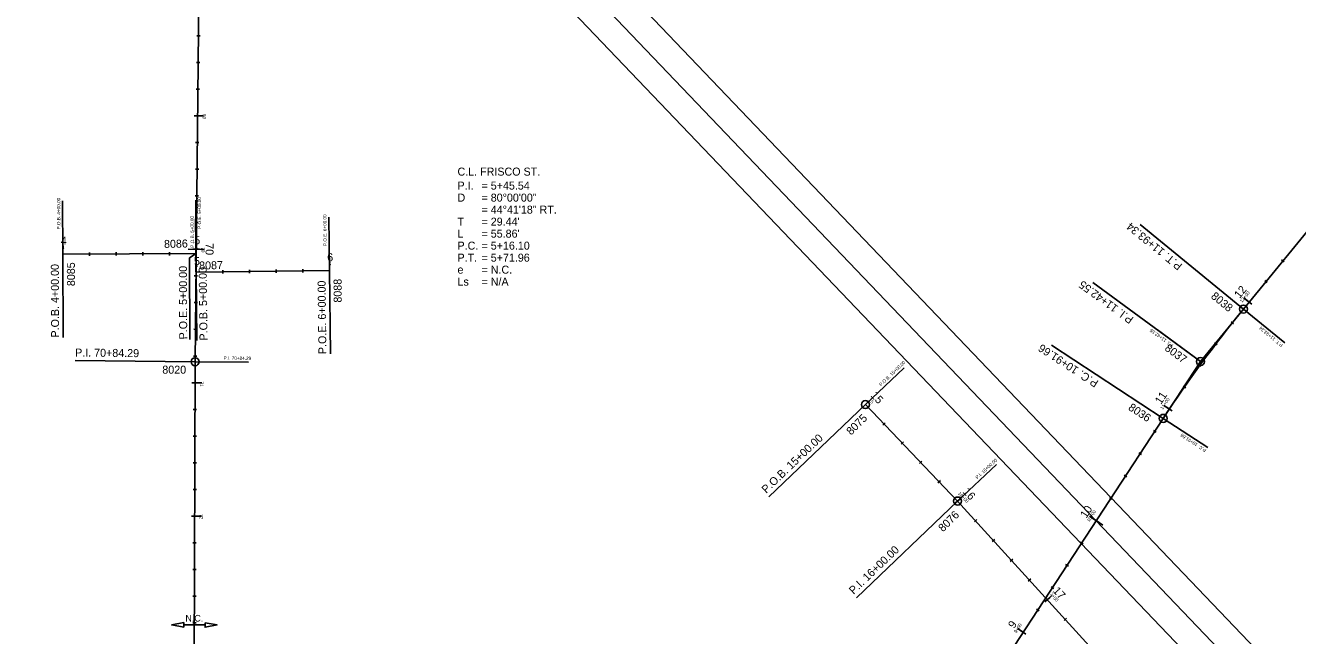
# Model space of a CAD drawing. Extents: x 1708585 to 1714116, y 541444 to 545437.
# Drawn here: x 1711863 to 1712816, y 543530 to 543987 of the extents above; entities that cross this region are included whole.
import ezdxf

# ---------------------------------------------------------------- set-up
doc = ezdxf.new("R2010")
doc.units = 0
for name, color, linetype in [('CL_Highway_2', 7, 'Continuous'), ('CL_Highway_2_40_PText', 7, 'Continuous'), ('CL_Highway_2_40_Sta', 7, 'Continuous'), ('CL_Highway_2_PText', 7, 'Continuous'), ('CL_Highway_2_Sta', 7, 'Continuous'), ('CL_Railroad', 7, 'Continuous'), ('CL_XS_1', 7, 'Continuous'), ('CL_XS_1_40_PText', 7, 'Continuous'), ('CL_XS_1_40_Sta', 7, 'Continuous'), ('CL_XS_1_PText', 7, 'Continuous'), ('CL_XS_1_Sta', 7, 'Continuous'), ('CL_XS_1_Sta_Minor_Text', 7, 'Continuous'), ('CL_XS_1_Tangent', 7, 'Continuous'), ('CL_XS_3', 7, 'Continuous'), ('CL_XS_3_40_PText', 7, 'Continuous'), ('CL_XS_3_40_Sta', 7, 'Continuous'), ('CL_XS_3_PText', 7, 'Continuous'), ('CL_XS_3_Sta', 7, 'Continuous'), ('CL_XS_3_Sta_Minor_Text', 7, 'Continuous'), ('CurveData_100', 7, 'Continuous'), ('Point_CL_Highway_2', 7, 'Continuous'), ('Point_CL_XS_1', 7, 'Continuous'), ('Point_CL_XS_3', 7, 'Continuous'), ('Point_Number', 7, 'Continuous'), ('R_SE_Slope', 7, 'Continuous')]:
    doc.layers.add(name, color=color, linetype=linetype)

msp = doc.modelspace()

# ---------------------------------------------------------------- linework, layer by layer
at = {"layer": 'CL_Highway_2'}
for p, q in [((1711994.54, 544190.95), (1711989.93, 543735.39)), ((1711989.93, 543735.39), (1711989.1, 543444.38))]:
    msp.add_line(p, q, dxfattribs=at)
at = {"layer": 'CL_Highway_2_40_PText'}
msp.add_lwpolyline([(1711989.93, 543735.39), (1712029.93, 543734.99)], dxfattribs=at)
at = {"layer": 'CL_Highway_2_40_Sta'}
for points in [[(1711993.65, 543979.66), (1711991.15, 543979.68)], [(1711993.45, 543959.66), (1711990.95, 543959.68)], [(1711993.25, 543939.66), (1711990.75, 543939.68)], [(1711994.3, 543919.65), (1711989.3, 543919.7)], [(1711992.84, 543899.66), (1711990.34, 543899.68)], [(1711992.64, 543879.66), (1711990.14, 543879.69)], [(1711992.44, 543859.66), (1711989.94, 543859.69)], [(1711992.24, 543839.66), (1711989.74, 543839.69)], [(1711993.28, 543819.65), (1711988.28, 543819.7)], [(1711991.83, 543799.66), (1711989.33, 543799.69)], [(1711991.63, 543779.67), (1711989.13, 543779.69)], [(1711991.43, 543759.67), (1711988.93, 543759.69)], [(1711991.22, 543739.67), (1711988.72, 543739.69)], [(1711992.39, 543719.67), (1711987.39, 543719.69)], [(1711991.08, 543699.68), (1711988.58, 543699.68)], [(1711991.02, 543679.68), (1711988.52, 543679.68)], [(1711990.96, 543659.68), (1711988.46, 543659.68)], [(1711990.91, 543639.68), (1711988.41, 543639.68)], [(1711992.1, 543619.67), (1711987.1, 543619.69)], [(1711990.79, 543599.68), (1711988.29, 543599.68)], [(1711990.74, 543579.68), (1711988.24, 543579.68)], [(1711990.68, 543559.68), (1711988.18, 543559.68)], [(1711990.62, 543539.68), (1711988.12, 543539.69)]]:
    msp.add_lwpolyline(points, dxfattribs=at)
at = {"layer": 'CL_Highway_2_PText'}
msp.add_lwpolyline([(1711989.93, 543735.39), (1711899.93, 543736.3)], dxfattribs=at)
at = {"layer": 'CL_Highway_2_Sta'}
for p, q in [((1711994.89, 543719.67), (1711989.89, 543719.68)), ((1711994.6, 543619.67), (1711989.6, 543619.68))]:
    msp.add_line(p, q, dxfattribs=at)
for points in [[(1711996.3, 543919.63), (1711991.8, 543919.67)], [(1711996.78, 543819.62), (1711984.78, 543819.74)]]:
    msp.add_lwpolyline(points, dxfattribs=at)
at = {"layer": 'CL_Railroad'}
for p, q in [((1710952.7, 545436.87), (1713371.13, 542906.81)), ((1710938.24, 545423.05), (1713356.67, 542892.99)), ((1710923.78, 545409.23), (1713342.21, 542879.17))]:
    msp.add_line(p, q, dxfattribs=at)
at = {"layer": 'CL_XS_1'}
for p, q in [((1712775.63, 543774.89), (1712930.47, 543963.94)), ((1712523.65, 543399.96), (1712715.52, 543692.96))]:
    msp.add_line(p, q, dxfattribs=at)
msp.add_arc((1713514.4, 543169.82), 954.93, 140.68144, 146.78172, dxfattribs=at)
at = {"layer": 'CL_XS_1_40_PText'}
for points in [[(1712775.63, 543774.89), (1712806.58, 543749.55)], [(1712743.39, 543735.53), (1712711.14, 543759.19)], [(1712715.52, 543692.96), (1712748.98, 543671.04)]]:
    msp.add_lwpolyline(points, dxfattribs=at)
at = {"layer": 'CL_XS_1_40_Sta'}
for points in [[(1712804.23, 543811.78), (1712806.17, 543810.2)], [(1712791.56, 543796.31), (1712793.49, 543794.73)], [(1712777.92, 543781.63), (1712781.79, 543778.46)], [(1712766.28, 543765.29), (1712768.23, 543763.74)], [(1712753.97, 543749.5), (1712755.96, 543747.98)], [(1712742, 543733.44), (1712744.02, 543731.97)], [(1712730.36, 543717.14), (1712732.41, 543715.71)], [(1712718.03, 543701.3), (1712722.19, 543698.52)], [(1712708.08, 543683.88), (1712710.17, 543682.51)], [(1712697.12, 543667.15), (1712699.21, 543665.78)], [(1712686.17, 543650.42), (1712688.26, 543649.05)], [(1712675.21, 543633.69), (1712677.3, 543632.32)], [(1712663.21, 543617.64), (1712667.39, 543614.9)], [(1712653.3, 543600.22), (1712655.39, 543598.86)], [(1712642.34, 543583.49), (1712644.43, 543582.12)], [(1712631.38, 543566.76), (1712633.47, 543565.39)], [(1712620.43, 543550.03), (1712622.52, 543548.66)], [(1712608.42, 543533.98), (1712612.61, 543531.24)]]:
    msp.add_lwpolyline(points, dxfattribs=at)
at = {"layer": 'CL_XS_1_PText'}
for points in [[(1712775.63, 543774.89), (1712698.27, 543838.26)], [(1712743.39, 543735.53), (1712662.77, 543794.68)], [(1712715.52, 543692.96), (1712631.86, 543747.74)]]:
    msp.add_lwpolyline(points, dxfattribs=at)
at = {"layer": 'CL_XS_1_Sta'}
for points in [[(1712775.99, 543783.22), (1712779.86, 543780.05)], [(1712715.95, 543702.69), (1712720.11, 543699.91)], [(1712660.28, 543619.56), (1712670.32, 543612.98)], [(1712606.33, 543535.35), (1712610.52, 543532.61)]]:
    msp.add_lwpolyline(points, dxfattribs=at)
at = {"layer": 'CL_XS_1_Tangent'}
for p, q in [((1712743.39, 543735.53), (1712775.63, 543774.89)), ((1712715.52, 543692.96), (1712743.39, 543735.53))]:
    msp.add_line(p, q, dxfattribs=at)
at = {"layer": 'CL_XS_3'}
for p, q in [((1711890.75, 543816.06), (1711990.75, 543816.45)), ((1711990.61, 543802.47), (1712090.6, 543803.69)), ((1712492.3, 543703.29), (1712561.4, 543631)), ((1712561.4, 543631), (1712682.55, 543497.88))]:
    msp.add_line(p, q, dxfattribs=at)
at = {"layer": 'CL_XS_3_40_PText'}
for points in [[(1711890.75, 543816.06), (1711890.6, 543856.06)], [(1711990.75, 543816.45), (1711990.59, 543856.45)], [(1711990.61, 543802.47), (1711990.12, 543842.47)], [(1712090.6, 543803.69), (1712090.11, 543843.69)], [(1712492.3, 543703.29), (1712521.22, 543730.93)], [(1712561.4, 543631), (1712590.65, 543658.28)]]:
    msp.add_lwpolyline(points, dxfattribs=at)
at = {"layer": 'CL_XS_3_40_Sta'}
for points in [[(1711890.74, 543818.56), (1711890.76, 543813.56)], [(1711910.75, 543817.39), (1711910.76, 543814.89)], [(1711930.75, 543817.46), (1711930.76, 543814.96)], [(1711950.75, 543817.54), (1711950.76, 543815.04)], [(1711970.75, 543817.62), (1711970.76, 543815.12)], [(1711990.74, 543818.95), (1711990.76, 543813.95)], [(1711990.58, 543804.97), (1711990.64, 543799.97)], [(1712010.59, 543803.96), (1712010.62, 543801.46)], [(1712030.59, 543804.21), (1712030.62, 543801.71)], [(1712050.59, 543804.45), (1712050.62, 543801.95)], [(1712070.59, 543804.7), (1712070.62, 543802.2)], [(1712090.57, 543806.19), (1712090.63, 543801.19)], [(1712494.11, 543705.01), (1712490.49, 543701.56)], [(1712507.02, 543689.69), (1712505.22, 543687.97)], [(1712520.84, 543675.24), (1712519.04, 543673.51)], [(1712534.66, 543660.78), (1712532.86, 543659.05)], [(1712548.48, 543646.32), (1712546.67, 543644.59)], [(1712563.21, 543632.73), (1712559.59, 543629.27)], [(1712575.78, 543617.05), (1712573.94, 543615.37)], [(1712589.25, 543602.26), (1712587.4, 543600.58)], [(1712602.71, 543587.47), (1712600.86, 543585.78)], [(1712616.17, 543572.67), (1712614.32, 543570.99)], [(1712630.55, 543558.72), (1712626.86, 543555.36)], [(1712643.09, 543543.09), (1712641.24, 543541.41)]]:
    msp.add_lwpolyline(points, dxfattribs=at)
at = {"layer": 'CL_XS_3_PText'}
for points in [[(1711890.75, 543816.06), (1711891, 543753.56)], [(1711990.75, 543816.45), (1711985.76, 543813.19), (1711986, 543752.17)], [(1711990.61, 543802.47), (1711991.23, 543751.35)], [(1712090.6, 543803.69), (1712091.37, 543741.2)], [(1712492.3, 543703.29), (1712420.01, 543634.19)], [(1712485.5, 543558.45), (1712561.4, 543631)]]:
    msp.add_lwpolyline(points, dxfattribs=at)
at = {"layer": 'CL_XS_3_Sta'}
for points in [[(1711990.73, 543822.45), (1711990.77, 543810.45)], [(1711890.73, 543820.56), (1711890.75, 543816.06)], [(1711990.54, 543808.47), (1711990.68, 543796.47)], [(1712090.55, 543808.19), (1712090.6, 543803.69)], [(1712496.64, 543707.43), (1712487.96, 543699.14)], [(1712564.65, 543634.11), (1712561.4, 543631)], [(1712632.03, 543560.07), (1712628.71, 543557.04)]]:
    msp.add_lwpolyline(points, dxfattribs=at)
at = {"layer": 'Point_CL_Highway_2'}
msp.add_circle((1711989.93, 543735.39), 3, dxfattribs=at)
at = {"layer": 'Point_CL_XS_1'}
for centre in [(1712775.63, 543774.89), (1712743.39, 543735.53), (1712715.52, 543692.96)]:
    msp.add_circle(centre, 3, dxfattribs=at)
at = {"layer": 'Point_CL_XS_3'}
for centre in [(1712492.3, 543703.29), (1712561.4, 543631)]:
    msp.add_circle(centre, 3, dxfattribs=at)
at = {"layer": 'R_SE_Slope'}
msp.add_line((1711981.37, 543538.15), (1711997.37, 543538.11), dxfattribs=at)
for points in [[(1711981.36, 543536.47), (1711981.37, 543539.84), (1711972.37, 543538.18)], [(1711997.37, 543539.8), (1711997.36, 543536.42), (1712006.37, 543538.08)]]:
    msp.add_lwpolyline(points, close=True, dxfattribs=at)

# ---------------------------------------------------------------- texts
at = {"layer": 'CL_Highway_2_40_PText'}
msp.add_text('P.I. 70+84.29', height=2.5, rotation=359.42018, dxfattribs=at).set_placement((1712011.25, 543736.93))
at = {"layer": 'CL_Highway_2_40_Sta'}
for s, rotation, p in [('69', 269.42018, (1711995.56, 543921.15)), ('70', 269.42018, (1711994.55, 543821.19)), ('71', 269.83643, (1711993.64, 543720.57)), ('72', 269.83643, (1711993.35, 543621.13))]:
    msp.add_text(s, height=2.5, rotation=rotation, dxfattribs=at).set_placement(p)
at = {"layer": 'CL_Highway_2_PText'}
msp.add_text('P.I. 70+84.29', height=6, rotation=359.42018, dxfattribs=at).set_placement((1711899.97, 543739.3))
at = {"layer": 'CL_Highway_2_Sta'}
msp.add_text('70', height=6, rotation=269.42018, dxfattribs=at).set_placement((1711997.83, 543824.26))
at = {"layer": 'CL_XS_1_40_PText'}
for s, rotation, p in [('P.I. 11+42.55', 143.73158, (1712723.21, 543748.16)), ('P.T. 11+93.34', 140.68144, (1712805.47, 543748.19)), ('P.C. 10+91.66', 146.78172, (1712748.02, 543669.58))]:
    msp.add_text(s, height=2.5, rotation=rotation, dxfattribs=at).set_placement(p)
at = {"layer": 'CL_XS_1_40_Sta'}
for s, rotation, p in [('12+00', 50.68144, (1712774.52, 543779.46)), ('11+00', 56.28162, (1712715.18, 543699.27)), ('10+00', 56.78172, (1712660.02, 543615.05)), ('9+00', 56.78172, (1712605.46, 543531.74))]:
    msp.add_text(s, height=2.5, rotation=rotation, dxfattribs=at).set_placement(p)
at = {"layer": 'CL_XS_1_PText'}
for s, rotation, p in [('P.T. 11+93.34', 140.68144, (1712730.3, 543808.14)), ('P.I. 11+42.55', 143.73158, (1712693.75, 543768.23)), ('P.C. 10+91.66', 146.78172, (1712667.53, 543720.79))]:
    msp.add_text(s, height=6, rotation=rotation, dxfattribs=at).set_placement(p)
at = {"layer": 'CL_XS_1_Sta'}
msp.add_text('10', height=6, rotation=56.78172, dxfattribs=at).set_placement((1712657.83, 543617.64))
at = {"layer": 'CL_XS_1_Sta_Minor_Text'}
for s, rotation, p in [('12', 50.68144, (1712772.73, 543782.4)), ('11', 56.28162, (1712713.74, 543702.97)), ('9', 56.78172, (1712603.72, 543535))]:
    msp.add_text(s, height=6, rotation=rotation, dxfattribs=at).set_placement(p)
at = {"layer": 'CL_XS_3_40_PText'}
for s, rotation, p in [('P.O.B. 4+00.00', 90.22332, (1711888.93, 543834.52)), ('P.O.E. 5+00.00', 90.22332, (1711994.43, 543835.03)), ('P.O.B. 5+00.00', 90.70071, (1711989.13, 543820.92)), ('P.O.E. 6+00.00', 90.70071, (1712088.63, 543822.14)), ('P.O.B. 15+00.00', 43.70736, (1712503.97, 543716.86)), ('P.I. 16+00.00', 43.00611, (1712576.2, 543647.2))]:
    msp.add_text(s, height=2.5, rotation=rotation, dxfattribs=at).set_placement(p)
at = {"layer": 'CL_XS_3_40_Sta'}
for s, rotation, p in [('4', 0.22332, (1711890.17, 543819.81)), ('5', 0.22332, (1711990.17, 543820.2)), ('5', 0.70071, (1711990, 543806.21)), ('6', 0.70071, (1712089.93, 543807.43)), ('15', 313.70736, (1712494.39, 543706.53)), ('16+00', 313.70736, (1712561.43, 543636.4)), ('17+00', 312.30486, (1712628.9, 543562.4))]:
    msp.add_text(s, height=2.5, rotation=rotation, dxfattribs=at).set_placement(p)
at = {"layer": 'CL_XS_3_PText'}
for s, rotation, p in [('P.O.B. 4+00.00', 90.22332, (1711888, 543753.55)), ('P.O.E. 5+00.00', 90.22332, (1711984, 543752.16)), ('P.O.B. 5+00.00', 90.70071, (1711999.24, 543751.34)), ('P.O.E. 6+00.00', 90.70071, (1712088.37, 543741.16)), ('P.O.B. 15+00.00', 43.70736, (1712417.94, 543636.36)), ('P.I. 16+00.00', 43.70736, (1712483.42, 543560.62))]:
    msp.add_text(s, height=6, rotation=rotation, dxfattribs=at).set_placement(p)
at = {"layer": 'CL_XS_3_Sta'}
for s, rotation, p in [('4', 0.22332, (1711889.31, 543823.05)), ('5', 0.22332, (1711989.31, 543823.44)), ('5', 0.70071, (1711989.13, 543807.8)), ('6', 0.70071, (1712088.96, 543810.67)), ('15', 313.70736, (1712495.81, 543709.75))]:
    msp.add_text(s, height=6, rotation=rotation, dxfattribs=at).set_placement(p)
at = {"layer": 'CL_XS_3_Sta_Minor_Text'}
for s, rotation, p in [('16', 313.70736, (1712564.81, 543637.56)), ('17', 312.30486, (1712632.37, 543563.41))]:
    msp.add_text(s, height=6, rotation=rotation, dxfattribs=at).set_placement(p)
at = {"layer": 'CurveData_100'}
for s, p in [('C.L. FRISCO ST.', (1712186.58, 543874.91)), ('P.I.', (1712186.58, 543864.41)), ('= 5+45.54', (1712204.58, 543864.41)), ('D', (1712186.58, 543855.41)), ('= 80%%d00\'00"', (1712204.58, 543855.41)), ('= 44%%d41\'18" RT.', (1712204.58, 543846.41)), ('T', (1712186.58, 543837.41)), ("= 29.44'", (1712204.58, 543837.41)), ('L', (1712186.58, 543828.41)), ("= 55.86'", (1712204.58, 543828.41)), ('P.C.', (1712186.58, 543819.41)), ('= 5+16.10', (1712204.58, 543819.41)), ('P.T.', (1712186.58, 543810.41)), ('= 5+71.96', (1712204.58, 543810.41)), ('e', (1712186.58, 543801.41)), ('= N.C.', (1712204.58, 543801.41)), ('Ls', (1712186.58, 543792.41)), ('= N/A', (1712204.58, 543792.41))]:
    msp.add_text(s, height=6, dxfattribs=at).set_placement(p)
at = {"layer": 'Point_Number'}
for s, rotation, p in [('8086', 1.17504, (1711966.67, 543820.66)), ('8085', 90.37191, (1711899.93, 543792.08)), ('8087', 1.17504, (1711992.99, 543804.5)), ('8088', 90.37191, (1712099.78, 543779.71)), ('8038', 320.68144, (1712750.75, 543783.64)), ('8037', 323.73158, (1712716.07, 543744.41)), ('8020', 359.83643, (1711965.35, 543726.46)), ('8036', 326.78172, (1712688.77, 543699.72)), ('8075', 44.73173, (1712481.56, 543679.98)), ('8076', 44.73173, (1712550.43, 543607.46))]:
    msp.add_text(s, height=6, rotation=rotation, dxfattribs=at).set_placement(p)
at = {"layer": 'R_SE_Slope'}
msp.add_text('N.C.', height=5, rotation=359.83643, dxfattribs=at).set_placement((1711982.66, 543540.65))

doc.saveas('drawing.dxf')
